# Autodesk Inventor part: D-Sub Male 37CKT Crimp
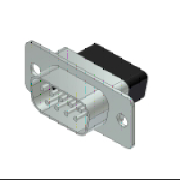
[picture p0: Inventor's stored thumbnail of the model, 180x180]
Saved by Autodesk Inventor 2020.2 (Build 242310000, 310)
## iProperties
Manager: www.cadconsulting.pl
Company: Fabian Stasiak CAD Consulting
IsCustomPart: 0
GlobalPropertyList: <PropertyList/>
Created: 2014-02
Part Number: D-Sub Male 37CKT Crimp
Material: Ogólny
Description: Wtyczka, złącze D-Sub
Document SubType Name: Modeling
Designer: F.Stasiak
Language: pl-PL
Size Designation: D-Sub Male Crimp 37CKT
Categories: <MemberInstance><Categories><Category DisplayName="Kable i wiązki przewodów" InternalName="e4a7e005-5e42-4d16-b293-125e7f0d0512" Mnemonic="CABLEANDHARNESS"><Cat
Density: 1 g/cm^3
Appearance: Domyślna
Catalog Web Link: www.expertbooks.pl
Author: F.Stasiak
Subject: Zbiór ćwiczeń. Autodesk Inventor 2020. Kurs Professional
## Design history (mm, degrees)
sketch "Sketch1"
  geometry: L1 (33.084, 6.299)-(-33.084, 6.299); L2 (-33.084, -6.299)-(33.084, -6.299); L3 (34.658, -4.724)-(34.658, 4.724); L4 (-34.658, 4.724)-(-34.658, -4.724); L5 (0, 6.299)-(0, -6.299); L6 (-31.75, 0)-(31.75, 0); L7 (34.658, 4.724)-(33.084, 4.724); L8 (33.084, 4.724)-(33.084, 6.299); L9 (34.658, -4.724)-(33.084, -4.724); L10 (33.084, -4.724)-(33.084, -6.299); L11 (-33.084, 6.299)-(-33.084, 4.724); L12 (-33.084, 4.724)-(-34.658, 4.724); L13 (-34.658, -4.724)-(-33.084, -4.724); L14 (-33.084, -4.724)-(-33.084, -6.299); C1 r 1.524 at (-31.75, 0); C2 r 1.524 at (31.75, 0); A1 r 1.575 centre (33.084, 4.724) between (34.658, 4.724) and (33.084, 6.299); A2 r 1.575 centre (33.084, -4.724) between (33.084, -6.299) and (34.658, -4.724); A3 r 1.575 centre (-33.084, 4.724) between (-33.084, 6.299) and (-34.658, 4.724); A4 r 1.575 centre (-33.084, -4.724) between (-34.658, -4.724) and (-33.084, -6.299); 7 further points
  constraints: 28 end point, 8 point on circle, 6 centre point, 6 midpoint, 5 perpendicular, 4 horizontal alignment, 4 vertical alignment, 3 equal radius, 3 parallel, 1 coincident
  dimensions: "d124" = 69.3166 distance between parallel lines of L3 L4 (derived); "d125" = 12.5984 distance between parallel lines of L2 L1; "d126" = 1.5748 radius of A1; "d134" = 3.048 diameter of C1; "d135" = 63.5 distance of L6.start L6.end (derived)
extrude "Wyciągnięcie1" new body sketch "Sketch1" stored distance "d4" = 0.762; taper "d5" = 0 deg
sketch "Sketch2"
  geometry: L1 (-33.084, 6.299)-(33.084, 6.299) reference; L2 (33.084, -6.299)-(-33.084, -6.299) reference; L3 (-24.382, -3.95)-(24.382, -3.95); L4 (24.879, 3.95)-(-24.879, 3.95); L5 (-27.381, 0.969)-(-26.884, -1.851); L6 (26.884, -1.851)-(27.381, 0.969); L7 (0, 3.95)-(0, -3.95); L8 (-27.419, 6.299)-(-27.419, -6.299); L9 (27.419, 6.299)-(27.419, -6.299); L10 (34.658, 4.724)-(34.658, -4.724) reference; L11 (-24.879, 4.356)-(24.879, 4.356); L12 (-24.382, -4.356)-(24.382, -4.356); L13 (-27.781, 0.898)-(-27.284, -1.921); L14 (27.781, 0.898)-(27.284, -1.921); A1 r 2.54 centre (-24.879, 1.41) between (-24.879, 3.95) and (-27.381, 0.969); A2 r 2.54 centre (-24.382, -1.41) between (-26.884, -1.851) and (-24.382, -3.95); A3 r 2.54 centre (24.382, -1.41) between (24.382, -3.95) and (26.884, -1.851); A4 r 2.54 centre (24.879, 1.41) between (27.381, 0.969) and (24.879, 3.95); A5 r 2.946 centre (-24.879, 1.41) between (-24.879, 4.356) and (-27.781, 0.898); A6 r 2.946 centre (24.382, -1.41) between (24.382, -4.356) and (27.284, -1.921); A7 r 2.946 centre (24.879, 1.41) between (27.781, 0.898) and (24.879, 4.356); A8 r 2.946 centre (-24.382, -1.41) between (-27.284, -1.921) and (-24.382, -4.356); 7 further points
  constraints: 22 end point, 16 point on circle, 8 centre point, 7 tangent, 6 midpoint, 4 coincident, 4 point on line, 3 equal radius, 3 parallel, 3 perpendicular, 2 vertical alignment, 1 horizontal alignment
  dimensions: "d127" = 2.54 radius of A4; "d129" = 7.8994 distance between parallel lines of L3 L4; "d131" = 10 deg angle of L7 L5; "d132" = 10 deg angle of L6 L7; "d133" = 54.8386 distance between parallel lines of L9 L8 (derived); "d198" = 0.49714 horizontal distance of A2.centre A1.centre; "d199" = 2.8194 vertical distance of A2.centre A1.centre; "d200" = 0.49714 horizontal distance of A3.centre A4.centre; "d201" = 2.8194 vertical distance of A3.centre A4.centre; "d292" = 0.4064 radial gap between concentric circles of A1 A5; "d293" = 0.4064 distance between parallel lines of L11 L4 (derived); "d294" = 0.4064 distance between parallel lines of L3 L12 (derived)
extrude "Wyciągnięcie2" join sketch "Sketch2" distance "d9" = 5.5372; taper "d10" = 0 deg
sketch "Sketch3"
  geometry: L1 (-28.929, 3.651)-(-27.545, -4.198); L2 (-25.994, -5.499)-(25.994, -5.499); L3 (27.378, 5.499)-(-27.378, 5.499); L4 (27.545, -4.198)-(28.904, 3.512); L5 (0, 5.499)-(0, -5.499); L6 (-28.953, 6.274)-(-28.953, -6.274); L7 (28.959, 6.274)-(28.959, -6.274); L8 (-33.084, 6.299)-(33.084, 6.299) reference; L9 (-34.658, -4.724)-(-34.658, 4.724) reference; L10 (33.084, -6.299)-(-33.084, -6.299) reference; L11 (-27.378, 5.499)-(-27.378, 3.924); L12 (-27.378, 3.924)-(-28.929, 3.651); L13 (-27.545, -4.198)-(-25.994, -3.924); L14 (-25.994, -3.924)-(-25.994, -5.499); L15 (25.994, -3.924)-(25.994, -5.499); L16 (25.994, -3.924)-(27.545, -4.198); L17 (27.378, 5.499)-(27.384, 3.924); L18 (27.384, 3.924)-(28.904, 3.512); L19 (34.658, 4.724)-(34.658, -4.724) reference; A1 r 1.575 centre (-25.994, -3.924) between (-27.545, -4.198) and (-25.994, -5.499); A2 r 1.575 centre (-27.378, 3.924) between (-27.378, 5.499) and (-28.929, 3.651); A3 r 1.575 centre (25.994, -3.924) between (25.994, -5.499) and (27.545, -4.198); A4 r 1.575 centre (27.384, 3.924) between (28.904, 3.512) and (27.378, 5.499); 5 further points
  constraints: 30 end point, 8 point on circle, 5 midpoint, 4 centre point, 4 parallel, 3 equal radius, 3 perpendicular, 2 horizontal alignment, 2 tangent, 2 vertical alignment
  dimensions: "d114" = 10.9982 distance between parallel lines of L2 L3; "d119" = 1.5748 radius of A4; "d120" = 10 deg angle of L5 L1; "d121" = 10 deg angle of L4 L5; "d122" = 57.912 distance between parallel lines of L7 L6 (derived); "d204" = 90 deg angle of L3 L11; "d205" = 100 deg angle of L11 L12; "d206" = 90 deg angle of L2 L14 (derived); "d207" = 80 deg angle of L14 L13 (derived); "d208" = 90 deg angle of L2 L15 (derived); "d209" = 80 deg angle of L16 L15 (derived); "d210" = 105.42 deg angle of L17 L18 (derived); "d211" = 90.2379 deg angle of L3 L17 (derived); "d295" = 1.38392 horizontal distance of L13.end L11.end; "d296" = 1.39046 horizontal distance of L15.start L17.end
extrude "Wyciągnięcie3" join sketch "Sketch3" distance "d14" = 3.937; taper "d15" = 0 deg
sketch "Sketch4"
  geometry: L1 (-27.378, 5.499)-(27.378, 5.499) reference; L2 (26.263, -2.574)-(27.096, 2.15); L3 (-25.062, -3.581)-(25.062, -3.581); L4 (25.895, 3.581)-(-25.895, 3.581); L5 (-27.096, 2.15)-(-26.263, -2.574); L6 (0, 3.581)-(0, -3.581); L7 (34.658, 4.724)-(34.658, -4.724) reference; L8 (-33.084, 6.299)-(33.084, 6.299) reference; L9 (-34.658, -4.724)-(-34.658, 4.724) reference; L10 (33.084, -6.299)-(-33.084, -6.299) reference; L11 (-27.115, 6.299)-(-27.115, -6.299); L12 (27.114, 6.299)-(27.114, -6.299); L13 (-27.545, -4.198)-(-28.929, 3.651) reference; L14 (25.994, -5.499)-(-25.994, -5.499) reference; L15 (-25.895, 2.362)-(-25.895, 3.581); L16 (-25.895, 2.362)-(-27.096, 2.15); L17 (-25.062, -2.362)-(-25.062, -3.581); L18 (-25.062, -2.362)-(-26.263, -2.574); L19 (25.062, -2.362)-(26.263, -2.574); L20 (25.062, -2.362)-(25.062, -3.581); L21 (25.895, 3.581)-(25.895, 2.362); L22 (25.895, 2.362)-(27.096, 2.15); C1 r 1.524 at (-31.75, 0) reference; C2 r 1.524 at (31.75, 0) reference; A1 r 1.219 centre (25.062, -2.362) between (25.062, -3.581) and (26.263, -2.574); A2 r 1.219 centre (25.895, 2.362) between (27.096, 2.15) and (25.895, 3.581); A3 r 1.219 centre (-25.062, -2.362) between (-26.263, -2.574) and (-25.062, -3.581); A4 r 1.219 centre (-25.895, 2.362) between (-25.895, 3.581) and (-27.096, 2.15); A5 r 1.575 centre (33.084, 4.724) between (34.658, 4.724) and (33.084, 6.299) reference; A6 r 1.575 centre (-33.084, 4.724) between (-33.084, 6.299) and (-34.658, 4.724) reference; A7 r 1.575 centre (-33.084, -4.724) between (-34.658, -4.724) and (-33.084, -6.299) reference; A8 r 1.575 centre (33.084, -4.724) between (33.084, -6.299) and (34.658, -4.724) reference; 3 further points
  constraints: 30 end point, 8 point on circle, 6 parallel, 5 perpendicular, 4 centre point, 4 midpoint, 4 point on line, 3 equal radius, 2 tangent, 1 horizontal alignment, 1 vertical alignment
  dimensions: "d136" = 7.1628 distance between parallel lines of L3 L4; "d137" = 1.2192 radius of A2; "d139" = 10 deg angle of L6 L5; "d140" = 10 deg angle of L2 L6; "d141" = 54.229 distance between parallel lines of L12 L11 (derived); "d212" = 90 deg angle of L4 L15; "d213" = 100 deg angle of L16 L15 (derived); "d214" = 90 deg angle of L3 L17 (derived); "d215" = 80 deg angle of L17 L18 (derived); "d216" = 90 deg angle of L3 L20 (derived); "d217" = 80 deg angle of L19 L20; "d218" = 90 deg angle of L4 L21 (derived); "d219" = 100 deg angle of L22 L21 (derived)
extrude "Wyciągnięcie4" join sketch "Sketch4" distance "d19" = 7.1882; taper "d20" = 0 deg
sketch "Sketch14"
  geometry: L1 (24.876, 3.404)-(24.876, 2.642); L2 (24.876, 2.642)-(24.781, 2.642); L3 (24.781, 2.642)-(24.781, 3.274); L4 (24.686, 3.16)-(24.686, 3.29); L5 (24.781, 3.404)-(24.876, 3.404); L6 (24.686, 3.29)-(24.781, 3.404); L7 (24.781, 3.274)-(24.686, 3.16); C1 r 1.105 at (24.828, 1.422); C2 r 1.105 at (23.462, -1.422); A1 r 1.219 centre (25.062, -2.362) between (25.062, -3.581) and (26.263, -2.574) reference; A2 r 1.219 centre (25.895, 2.362) between (27.096, 2.15) and (25.895, 3.581) reference; 1 further point
  constraints: 14 end point, 2 centre point, 1 midpoint, 1 vertical alignment
  dimensions: "d144" = 2.2098 diameter of C1; "d162" = 2.2098 diameter of C2; "d181" = 0.09525 distance of L1.end L2.end; "d182" = 40.0062 deg angle of L3 L7; "d183" = 0.1297 distance of L4.start L4.end; "d184" = 0.09525 distance of L5.start L1.start; "d185" = 0.762 distance of L1.start L1.end; "d186" = 0.6323 distance of L2.end L3.end; "d187" = 0.14816 distance of L4.end L5.start; "d188" = 0.14816 distance of L3.end L4.start; "d189" = 40.0062 deg angle of L4 L7; "d190" = 139.994 deg angle of L4 L6; "d297" = 1.0668 horizontal distance of A2.centre C1.centre; "d298" = 0.9398 vertical distance of C1.centre A2.centre; "d299" = 1.6002 horizontal distance of A1.centre C2.centre; "d300" = 0.9398 vertical distance of A1.centre C2.centre
sketch "Sketch15"
  geometry: C1 r 0.533 at (-24.841, 1.422); C2 r 0.533 at (-23.47, -1.422); A1 r 2.54 centre (24.879, 1.41) between (27.381, 0.969) and (24.879, 3.95); A2 r 2.54 centre (24.382, -1.41) between (24.382, -3.95) and (26.884, -1.851); A3 r 2.54 centre (-24.879, 1.41) between (-24.879, 3.95) and (-27.381, 0.969) reference; A4 r 2.54 centre (-24.382, -1.41) between (-26.884, -1.851) and (-24.382, -3.95) reference
  constraints: 4 centre point, 4 point on circle, 1 equal radius
  dimensions: "d149" = 1.0668 diameter of C1; "d301" = 0.0381 horizontal distance of A3.centre C1.centre; "d302" = 0.0127 vertical distance of A3.centre C1.centre; "d303" = 0.91256 horizontal distance of A4.centre C2.centre; "d304" = 0.0127 vertical distance of A4.centre C2.centre
sketch "Sketch16"
  geometry: L1 (24.876, 2.642)-(24.781, 2.642) reference; L2 (24.781, 2.642)-(24.781, 3.274) reference; L3 (24.781, 3.274)-(24.686, 3.16) reference; L4 (24.686, 3.16)-(24.686, 3.29) reference; L5 (24.686, 3.29)-(24.781, 3.404) reference; L6 (24.781, 3.404)-(24.876, 3.404) reference; L7 (24.876, 3.404)-(24.876, 2.642) reference; L8 (25.062, -3.581)-(-25.062, -3.581) reference; L9 (27.096, 2.15)-(26.263, -2.574) reference; L10 (-25.895, 3.581)-(25.895, 3.581) reference; L11 (-26.263, -2.574)-(-27.096, 2.15) reference; L12 (25.062, -3.581)-(-25.062, -3.581) reference; L13 (27.096, 2.15)-(26.263, -2.574) reference; L14 (-25.895, 3.581)-(25.895, 3.581) reference; L15 (-26.263, -2.574)-(-27.096, 2.15) reference; A1 r 1.219 centre (-25.895, 2.362) between (-25.895, 3.581) and (-27.096, 2.15) reference; A2 r 1.219 centre (25.062, -2.362) between (25.062, -3.581) and (26.263, -2.574) reference; A3 r 1.219 centre (25.895, 2.362) between (27.096, 2.15) and (25.895, 3.581) reference; A4 r 1.219 centre (-25.062, -2.362) between (-26.263, -2.574) and (-25.062, -3.581) reference; A5 r 1.219 centre (25.062, -2.362) between (25.062, -3.581) and (26.263, -2.574) reference; A6 r 1.219 centre (25.895, 2.362) between (27.096, 2.15) and (25.895, 3.581) reference; A7 r 1.219 centre (-25.062, -2.362) between (-26.263, -2.574) and (-25.062, -3.581) reference; 37 further points
  dimensions: "P1C" = 1.0668 horizontal distance of A3.centre point (24.828, 1.422); "P1R" = 0.9398 vertical distance of A3.centre point (24.828, 1.422); "P2C" = 3.81 horizontal distance of A3.centre point (22.085, 1.422); "P2R" = 0.9398 vertical distance of A3.centre point (22.085, 1.422); "P3C" = 6.5532 horizontal distance of A6.centre point (19.342, 1.422); "P3R" = 0.9398 vertical distance of A3.centre point (19.342, 1.422); "P4C" = 9.2964 horizontal distance of A6.centre point (16.599, 1.422); "P4R" = 0.9398 vertical distance of A3.centre point (16.599, 1.422); "P5C" = 12.0396 horizontal distance of A3.centre point (13.856, 1.422); "P5R" = 0.9398 vertical distance of A6.centre point (13.856, 1.422); "P6C" = 14.7828 horizontal distance of A3.centre point (11.112, 1.422); "P6R" = 0.9398 vertical distance of A3.centre point (11.112, 1.422); "P7C" = 17.526 horizontal distance of A3.centre point (8.369, 1.422); "P7R" = 0.9398 vertical distance of A3.centre point (8.369, 1.422); "P8C" = 20.2692 horizontal distance of A3.centre point (5.626, 1.422); "P8R" = 0.9398 vertical distance of A3.centre point (5.626, 1.422); "P9C" = 23.0124 horizontal distance of A6.centre point (2.883, 1.422); "P9R" = 0.9398 vertical distance of A3.centre point (2.883, 1.422); "P10C" = 25.7556 horizontal distance of A6.centre point (0.14, 1.422); "P10R" = 0.9398 vertical distance of A3.centre point (0.14, 1.422); "P11C" = 28.4988 horizontal distance of A6.centre point (-2.604, 1.422); "P11R" = 0.9398 vertical distance of A3.centre point (-2.604, 1.422); "P12C" = 31.242 horizontal distance of A3.centre point (-5.347, 1.422); "P12R" = 0.9398 vertical distance of A3.centre point (-5.347, 1.422); "P13C" = 33.9852 horizontal distance of A3.centre point (-8.09, 1.422); "P13R" = 0.9398 vertical distance of A3.centre point (-8.09, 1.422); "P14C" = 36.7284 horizontal distance of A3.centre point (-10.833, 1.422); "P14R" = 0.9398 vertical distance of A3.centre point (-10.833, 1.422); "P15C" = 39.4716 horizontal distance of A3.centre point (-13.576, 1.422); "P15R" = 0.9398 vertical distance of A3.centre point (-13.576, 1.422); "P16C" = 42.2148 horizontal distance of A3.centre point (-16.32, 1.422); "P16R" = 0.9398 vertical distance of A3.centre point (-16.32, 1.422); "P17C" = 44.958 horizontal distance of A3.centre point (-19.063, 1.422); "P17R" = 0.9398 vertical distance of A3.centre point (-19.063, 1.422); "P18C" = 47.7012 horizontal distance of A3.centre point (-21.806, 1.422); "P18R" = 0.9398 vertical distance of A6.centre point (-21.806, 1.422); "P19C" = 50.4444 horizontal distance of A3.centre point (-24.549, 1.422); "P19R" = 0.9398 vertical distance of A3.centre point (-24.549, 1.422); "P20C" = 2.4384 horizontal distance of point (23.457, -1.422) A3.centre; "P20R" = 3.7846 vertical distance of A3.centre point (23.457, -1.422); "P21C" = 5.1816 horizontal distance of A6.centre point (20.714, -1.422); "P21R" = 3.7846 vertical distance of A3.centre point (20.714, -1.422); "P22C" = 7.9248 horizontal distance of A3.centre point (17.97, -1.422); "P22R" = 3.7846 vertical distance of A3.centre point (17.97, -1.422); "P23C" = 10.668 horizontal distance of A3.centre point (15.227, -1.422); "P23R" = 3.7846 vertical distance of A3.centre point (15.227, -1.422); "P24C" = 13.4112 horizontal distance of A3.centre point (12.484, -1.422); "P24R" = 3.7846 vertical distance of A3.centre point (12.484, -1.422); "P25C" = 16.1544 horizontal distance of A6.centre point (9.741, -1.422); "P25R" = 3.7846 vertical distance of A3.centre point (9.741, -1.422); "P26C" = 18.8976 horizontal distance of A3.centre point (6.998, -1.422); "P26R" = 3.7846 vertical distance of A3.centre point (6.998, -1.422); "P27C" = 21.6408 horizontal distance of A3.centre point (4.254, -1.422); "P27R" = 3.7846 vertical distance of A3.centre point (4.254, -1.422); "P28C" = 24.384 horizontal distance of A3.centre point (1.511, -1.422); "P28R" = 3.7846 vertical distance of A3.centre point (1.511, -1.422); "P29C" = 27.1272 horizontal distance of A3.centre point (-1.232, -1.422); "P29R" = 3.7846 vertical distance of A3.centre point (-1.232, -1.422); "P30C" = 29.8704 horizontal distance of A3.centre point (-3.975, -1.422); "P30R" = 3.7846 vertical distance of A3.centre point (-3.975, -1.422); "P31C" = 32.6136 horizontal distance of A3.centre point (-6.718, -1.422); "P31R" = 3.7846 vertical distance of A3.centre point (-6.718, -1.422); "P32C" = 35.4584 horizontal distance of A3.centre point (-9.563, -1.422); "P32R" = 3.7846 vertical distance of A3.centre point (-9.563, -1.422)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
node "1"
node "2"
node "3"
node "4"
node "5"
node "6"
node "7"
node "8"
node "9"
node "10"
node "11"
node "12"
node "13"
node "14"
node "15"
node "16"
node "17"
node "18"
node "19"
node "20"
node "21"
node "22"
node "23"
node "24"
node "25"
node "26"
node "27"
node "28"
node "29"
node "30"
node "31"
node "32"
node "33"
node "34"
node "35"
node "36"
node "37"
body "Solid1"
extrude "Wyciągnięcie proste15" cut sketch "Sketch14" stored distance "d147" = 25.4; taper "d148" = 0 deg
extrude "Wyciągnięcie proste16" join sketch "Sketch15" distance "d152" = 5.08; taper "d153" = 0 deg
pattern_linear "Wzór prostokątny7" dims "d159" = 2.7432 (derived)
extrude "Wyciągnięcie proste17" cut sketch "Sketch14" stored distance "d165" = 25.4; taper "d166" = 0 deg
extrude "Wyciągnięcie proste18" join sketch "Sketch15" distance "d171" = 5.08; taper "d172" = 0 deg
pattern_linear "Wzór prostokątny8" dims "d178" = 2.7432 (derived)
extrude "Wyciągnięcie proste19" join sketch "Sketch14" distance "d193" = 0.0254; taper "d194" = 0 deg
node "Projected Loop2"
other parameters: "DimA" = 69.3166 [user parameter], "DimB" = 63.5 [user parameter], "DimC" = 54.8386 [user parameter], "DimD" = 57.912 [user parameter], "DimE" = 54.229 [user parameter], "PinPitch" = 2.7432 [user parameter]
